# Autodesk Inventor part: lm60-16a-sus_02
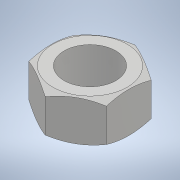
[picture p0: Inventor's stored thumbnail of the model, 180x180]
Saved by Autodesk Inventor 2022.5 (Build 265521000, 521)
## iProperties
Part Number: lm60-16a-sus_02
Material: 一般
Document SubType Name: Modeling
Designer: ImaoCorp
Density: 1 g/cm^3
Appearance: 既定
Author: ImaoCorp
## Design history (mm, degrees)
feature "lm60-16a-sus_02"
node "ソリッド1"
